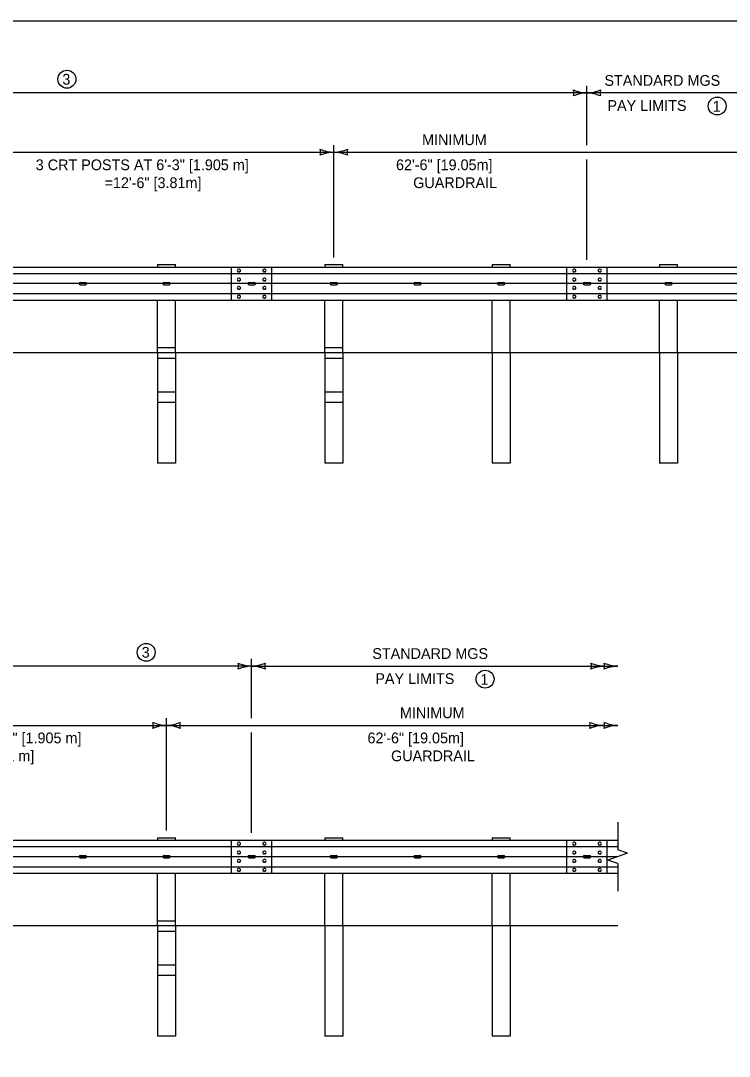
# Model space of a CAD drawing. Extents: x 49991.4 to 50021, y 49987.6 to 50011.4.
# Drawn here: x 50007.16 to 50011.12, y 49993.22 to 49999 of the extents above; entities that cross this region are included whole.
import ezdxf

# ---------------------------------------------------------------- set-up
doc = ezdxf.new("R2010")
doc.units = 0
for name, color, linetype in [('Level 1', 7, 'Continuous'), ('Level 2', 7, 'Continuous'), ('Level 3', 7, 'Continuous'), ('Level 4', 7, 'Continuous'), ('Level 5', 7, 'Continuous'), ('Level 6', 7, 'Continuous')]:
    doc.layers.add(name, color=color, linetype=linetype)

msp = doc.modelspace()

# ---------------------------------------------------------------- linework, layer by layer
at = {"layer": 'Level 1'}
for p, q in [((50007.9289, 49997.6379), (50007.9289, 49997.6246)), ((50007.9289, 49997.6379), (50008.0288, 49997.6379)), ((50008.0288, 49997.6246), (50008.0288, 49997.6379)), ((50008.8633, 49997.6379), (50008.8633, 49997.6246)), ((50008.8633, 49997.6379), (50008.9633, 49997.6379)), ((50008.9633, 49997.6246), (50008.9633, 49997.6379)), ((50009.7977, 49997.6379), (50009.7977, 49997.6246)), ((50009.7977, 49997.6379), (50009.8977, 49997.6379)), ((50009.8977, 49997.6246), (50009.8977, 49997.6379)), ((50010.7322, 49997.6379), (50010.7322, 49997.6246)), ((50010.7322, 49997.6379), (50010.8321, 49997.6379)), ((50010.8321, 49997.6246), (50010.8321, 49997.6379)), ((50000.0289, 49997.6246), (50011.2949, 49997.6246)), ((50000.0289, 49997.5886), (50011.2949, 49997.5886)), ((50008.3411, 49997.4394), (50008.3411, 49997.6239)), ((50008.3852, 49997.6123), (50008.3816, 49997.6123)), ((50008.3852, 49997.5973), (50008.3816, 49997.5973)), ((50008.5275, 49997.6123), (50008.5239, 49997.6123)), ((50008.5275, 49997.5973), (50008.5239, 49997.5973)), ((50010.2135, 49997.4394), (50010.2135, 49997.6239)), ((50010.2577, 49997.6123), (50010.2541, 49997.6123)), ((50010.2577, 49997.5973), (50010.2541, 49997.5973)), ((50010.3999, 49997.6123), (50010.3963, 49997.6123)), ((50010.3999, 49997.5973), (50010.3963, 49997.5973)), ((50007.497, 49997.5386), (50007.5262, 49997.5386)), ((50007.497, 49997.5261), (50007.5262, 49997.5261)), ((50007.9642, 49997.5386), (50007.9934, 49997.5386)), ((50007.9642, 49997.5261), (50007.9934, 49997.5261)), ((50008.3852, 49997.5624), (50008.3816, 49997.5624)), ((50008.3852, 49997.5474), (50008.3816, 49997.5474)), ((50008.3852, 49997.516), (50008.3816, 49997.516)), ((50008.4397, 49997.5386), (50008.4689, 49997.5386)), ((50008.4397, 49997.5261), (50008.4689, 49997.5261)), ((50008.5275, 49997.5624), (50008.5239, 49997.5624)), ((50008.5275, 49997.5474), (50008.5239, 49997.5474)), ((50008.5275, 49997.516), (50008.5239, 49997.516)), ((50008.8987, 49997.5386), (50008.9279, 49997.5386)), ((50008.8987, 49997.5261), (50008.9279, 49997.5261)), ((50009.3659, 49997.5386), (50009.3951, 49997.5386)), ((50009.3659, 49997.5261), (50009.3951, 49997.5261)), ((50009.8331, 49997.5386), (50009.8623, 49997.5386)), ((50009.8331, 49997.5261), (50009.8623, 49997.5261)), ((50010.2577, 49997.5624), (50010.2541, 49997.5624)), ((50010.2577, 49997.5474), (50010.2541, 49997.5474)), ((50010.2577, 49997.516), (50010.2541, 49997.516)), ((50010.3122, 49997.5386), (50010.3413, 49997.5386)), ((50010.3122, 49997.5261), (50010.3413, 49997.5261)), ((50010.3999, 49997.5624), (50010.3963, 49997.5624)), ((50010.3999, 49997.5474), (50010.3963, 49997.5474)), ((50010.3999, 49997.516), (50010.3963, 49997.516)), ((50010.7676, 49997.5386), (50010.7967, 49997.5386)), ((50010.7676, 49997.5261), (50010.7967, 49997.5261)), ((50000.0289, 49997.4761), (50011.2949, 49997.4761)), ((50008.3852, 49997.5009), (50008.3816, 49997.5009)), ((50008.3852, 49997.4661), (50008.3816, 49997.4661)), ((50008.5275, 49997.5009), (50008.5239, 49997.5009)), ((50008.5275, 49997.4661), (50008.5239, 49997.4661)), ((50010.2577, 49997.5009), (50010.2541, 49997.5009)), ((50010.2577, 49997.4661), (50010.2541, 49997.4661)), ((50010.3999, 49997.5009), (50010.3963, 49997.5009)), ((50010.3999, 49997.4661), (50010.3963, 49997.4661)), ((50000.0289, 49997.4401), (50011.2949, 49997.4401)), ((50007.9289, 49997.1457), (50007.9289, 49997.4401)), ((50008.0288, 49997.1457), (50008.0288, 49997.4401)), ((50008.3852, 49997.451), (50008.3816, 49997.451)), ((50008.5275, 49997.451), (50008.5239, 49997.451)), ((50008.8633, 49997.1457), (50008.8633, 49997.4401)), ((50008.9632, 49997.1457), (50008.9632, 49997.4401)), ((50009.7977, 49997.1457), (50009.7977, 49997.4401)), ((50009.8976, 49997.1457), (50009.8976, 49997.4401)), ((50010.2577, 49997.451), (50010.2541, 49997.451)), ((50010.3999, 49997.451), (50010.3963, 49997.451)), ((50010.7322, 49997.1457), (50010.7322, 49997.4401)), ((50010.8321, 49997.1457), (50010.8321, 49997.4401)), ((50011.2949, 49997.1457), (50000.0289, 49997.1457)), ((50000.0289, 49994.4263), (50010.4985, 49994.4263)), ((50000.0289, 49994.3903), (50010.4985, 49994.3903)), ((50007.9289, 49994.4396), (50007.9289, 49994.4263)), ((50007.9289, 49994.4396), (50008.0288, 49994.4396)), ((50008.0288, 49994.4263), (50008.0288, 49994.4396)), ((50008.3411, 49994.241), (50008.3411, 49994.4256)), ((50008.3852, 49994.414), (50008.3816, 49994.414)), ((50008.3852, 49994.3989), (50008.3816, 49994.3989)), ((50008.5275, 49994.414), (50008.5239, 49994.414)), ((50008.5275, 49994.3989), (50008.5239, 49994.3989)), ((50008.8633, 49994.4396), (50008.8633, 49994.4263)), ((50008.8633, 49994.4396), (50008.9633, 49994.4396)), ((50008.9633, 49994.4263), (50008.9633, 49994.4396)), ((50009.7977, 49994.4396), (50009.7977, 49994.4263)), ((50009.7977, 49994.4396), (50009.8977, 49994.4396)), ((50009.8977, 49994.4263), (50009.8977, 49994.4396)), ((50010.2135, 49994.241), (50010.2135, 49994.4256)), ((50010.2577, 49994.414), (50010.2541, 49994.414)), ((50010.2577, 49994.3989), (50010.2541, 49994.3989)), ((50010.3999, 49994.414), (50010.3963, 49994.414)), ((50010.3999, 49994.3989), (50010.3963, 49994.3989)), ((50007.497, 49994.3403), (50007.5262, 49994.3403)), ((50007.9642, 49994.3403), (50007.9934, 49994.3403)), ((50008.3852, 49994.3641), (50008.3816, 49994.3641)), ((50008.3852, 49994.349), (50008.3816, 49994.349)), ((50008.4397, 49994.3403), (50008.4689, 49994.3403)), ((50008.5275, 49994.3641), (50008.5239, 49994.3641)), ((50008.5275, 49994.349), (50008.5239, 49994.349)), ((50008.8987, 49994.3403), (50008.9279, 49994.3403)), ((50009.3659, 49994.3403), (50009.3951, 49994.3403)), ((50009.8331, 49994.3403), (50009.8623, 49994.3403)), ((50010.2577, 49994.3641), (50010.2541, 49994.3641)), ((50010.2577, 49994.349), (50010.2541, 49994.349)), ((50010.3122, 49994.3403), (50010.3413, 49994.3403)), ((50010.3999, 49994.3641), (50010.3963, 49994.3641)), ((50010.3999, 49994.349), (50010.3963, 49994.349)), ((50000.0289, 49994.2777), (50010.4985, 49994.2777)), ((50007.497, 49994.3278), (50007.5262, 49994.3278)), ((50007.9642, 49994.3278), (50007.9934, 49994.3278)), ((50008.3852, 49994.3176), (50008.3816, 49994.3176)), ((50008.3852, 49994.3025), (50008.3816, 49994.3025)), ((50008.4397, 49994.3278), (50008.4689, 49994.3278)), ((50008.5275, 49994.3176), (50008.5239, 49994.3176)), ((50008.5275, 49994.3025), (50008.5239, 49994.3025)), ((50008.8987, 49994.3278), (50008.9279, 49994.3278)), ((50009.3659, 49994.3278), (50009.3951, 49994.3278)), ((50009.8331, 49994.3278), (50009.8623, 49994.3278)), ((50010.2577, 49994.3176), (50010.2541, 49994.3176)), ((50010.2577, 49994.3025), (50010.2541, 49994.3025)), ((50010.3122, 49994.3278), (50010.3413, 49994.3278)), ((50010.3999, 49994.3176), (50010.3963, 49994.3176)), ((50010.3999, 49994.3025), (50010.3963, 49994.3025)), ((50000.0289, 49994.2417), (50010.4985, 49994.2417)), ((50007.9289, 49993.9473), (50007.9289, 49994.2417)), ((50008.0288, 49993.9473), (50008.0288, 49994.2417)), ((50008.3852, 49994.2677), (50008.3816, 49994.2677)), ((50008.3852, 49994.2526), (50008.3816, 49994.2526)), ((50008.5275, 49994.2677), (50008.5239, 49994.2677)), ((50008.5275, 49994.2526), (50008.5239, 49994.2526)), ((50008.8633, 49993.9473), (50008.8633, 49994.2417)), ((50008.9632, 49993.9473), (50008.9632, 49994.2417)), ((50009.7977, 49993.9473), (50009.7977, 49994.2417)), ((50009.8976, 49993.9473), (50009.8976, 49994.2417)), ((50010.2577, 49994.2677), (50010.2541, 49994.2677)), ((50010.2577, 49994.2526), (50010.2541, 49994.2526)), ((50010.3999, 49994.2677), (50010.3963, 49994.2677)), ((50010.3999, 49994.2526), (50010.3963, 49994.2526)), ((50010.4985, 49993.9473), (50000.0289, 49993.9473))]:
    msp.add_line(p, q, dxfattribs=at)
msp.add_lwpolyline([(49999.3835, 49998.9992), (50016.7501, 49998.9992), (50016.7501, 49987.7988), (49999.3835, 49987.7988)], close=True, dxfattribs=at)
for centre, start, end in [((50007.497, 49997.5324), 90, 180), ((50007.497, 49997.5324), 180, 270), ((50007.5262, 49997.5324), 360, 90), ((50007.5262, 49997.5324), 270, 0), ((50007.9642, 49997.5324), 90, 180), ((50007.9642, 49997.5324), 180, 270), ((50007.9934, 49997.5324), 360, 90), ((50007.9934, 49997.5324), 270, 0), ((50008.4397, 49997.5324), 90, 180), ((50008.4397, 49997.5324), 180, 270), ((50008.4689, 49997.5324), 360, 90), ((50008.4689, 49997.5324), 270, 0), ((50008.8987, 49997.5324), 90, 180), ((50008.8987, 49997.5324), 180, 270), ((50008.9279, 49997.5324), 360, 90), ((50008.9279, 49997.5324), 270, 0), ((50009.3659, 49997.5324), 90, 180), ((50009.3659, 49997.5324), 180, 270), ((50009.3951, 49997.5324), 360, 90), ((50009.3951, 49997.5324), 270, 0), ((50009.8331, 49997.5324), 90, 180), ((50009.8331, 49997.5324), 180, 270), ((50009.8623, 49997.5324), 360, 90), ((50009.8623, 49997.5324), 270, 0), ((50010.3122, 49997.5324), 90, 180), ((50010.3122, 49997.5324), 180, 270), ((50010.3413, 49997.5324), 360, 90), ((50010.3413, 49997.5324), 270, 0), ((50010.7676, 49997.5324), 90, 180), ((50010.7676, 49997.5324), 180, 270), ((50010.7967, 49997.5324), 360, 90), ((50010.7967, 49997.5324), 270, 0), ((50007.497, 49994.334), 90, 180), ((50007.497, 49994.334), 180, 270), ((50007.5262, 49994.334), 360, 90), ((50007.5262, 49994.334), 270, 0), ((50007.9642, 49994.334), 90, 180), ((50007.9642, 49994.334), 180, 270), ((50007.9934, 49994.334), 360, 90), ((50007.9934, 49994.334), 270, 0), ((50008.4397, 49994.334), 90, 180), ((50008.4397, 49994.334), 180, 270), ((50008.4689, 49994.334), 360, 90), ((50008.4689, 49994.334), 270, 0), ((50008.8987, 49994.334), 90, 180), ((50008.8987, 49994.334), 180, 270), ((50008.9279, 49994.334), 360, 90), ((50008.9279, 49994.334), 270, 0), ((50009.3659, 49994.334), 90, 180), ((50009.3659, 49994.334), 180, 270), ((50009.3951, 49994.334), 360, 90), ((50009.3951, 49994.334), 270, 0), ((50009.8331, 49994.334), 90, 180), ((50009.8331, 49994.334), 180, 270), ((50009.8623, 49994.334), 360, 90), ((50009.8623, 49994.334), 270, 0), ((50010.3122, 49994.334), 90, 180), ((50010.3122, 49994.334), 180, 270), ((50010.3413, 49994.334), 360, 90), ((50010.3413, 49994.334), 270, 0)]:
    msp.add_arc(centre, 0.00625, start, end, dxfattribs=at)
for centre, start_param, end_param in [((50008.3816, 49997.6048), 1.570796, 4.712389), ((50008.3852, 49997.6048), 4.712389, 7.853982), ((50008.5239, 49997.6048), 1.570796, 4.712389), ((50008.5275, 49997.6048), 4.712389, 7.853982), ((50010.2541, 49997.6048), 1.570796, 4.712389), ((50010.2577, 49997.6048), 4.712389, 7.853982), ((50010.3963, 49997.6048), 1.570796, 4.712389), ((50010.3999, 49997.6048), 4.712389, 7.853982), ((50008.3816, 49997.5549), 1.570796, 4.712389), ((50008.3816, 49997.5084), 1.570796, 4.712389), ((50008.3852, 49997.5549), 4.712389, 7.853982), ((50008.3852, 49997.5084), 4.712389, 7.853982), ((50008.5239, 49997.5549), 1.570796, 4.712389), ((50008.5239, 49997.5084), 1.570796, 4.712389), ((50008.5275, 49997.5549), 4.712389, 7.853982), ((50008.5275, 49997.5084), 4.712389, 7.853982), ((50010.2541, 49997.5549), 1.570796, 4.712389), ((50010.2541, 49997.5084), 1.570796, 4.712389), ((50010.2577, 49997.5549), 4.712389, 7.853982), ((50010.2577, 49997.5084), 4.712389, 7.853982), ((50010.3963, 49997.5549), 1.570796, 4.712389), ((50010.3963, 49997.5084), 1.570796, 4.712389), ((50010.3999, 49997.5549), 4.712389, 7.853982), ((50010.3999, 49997.5084), 4.712389, 7.853982), ((50008.3816, 49997.4585), 1.570796, 4.712389), ((50008.3852, 49997.4585), 4.712389, 7.853982), ((50008.5239, 49997.4585), 1.570796, 4.712389), ((50008.5275, 49997.4585), 4.712389, 7.853982), ((50010.2541, 49997.4585), 1.570796, 4.712389), ((50010.2577, 49997.4585), 4.712389, 7.853982), ((50010.3963, 49997.4585), 1.570796, 4.712389), ((50010.3999, 49997.4585), 4.712389, 7.853982), ((50008.3816, 49994.4065), 1.570796, 4.712389), ((50008.3852, 49994.4065), 4.712389, 7.853982), ((50008.5239, 49994.4065), 1.570796, 4.712389), ((50008.5275, 49994.4065), 4.712389, 7.853982), ((50010.2541, 49994.4065), 1.570796, 4.712389), ((50010.2577, 49994.4065), 4.712389, 7.853982), ((50010.3963, 49994.4065), 1.570796, 4.712389), ((50010.3999, 49994.4065), 4.712389, 7.853982), ((50008.3816, 49994.3566), 1.570796, 4.712389), ((50008.3852, 49994.3566), 4.712389, 7.853982), ((50008.5239, 49994.3566), 1.570796, 4.712389), ((50008.5275, 49994.3566), 4.712389, 7.853982), ((50010.2541, 49994.3566), 1.570796, 4.712389), ((50010.2577, 49994.3566), 4.712389, 7.853982), ((50010.3963, 49994.3566), 1.570796, 4.712389), ((50010.3999, 49994.3566), 4.712389, 7.853982), ((50008.3816, 49994.3101), 1.570796, 4.712389), ((50008.3852, 49994.3101), 4.712389, 7.853982), ((50008.5239, 49994.3101), 1.570796, 4.712389), ((50008.5275, 49994.3101), 4.712389, 7.853982), ((50010.2541, 49994.3101), 1.570796, 4.712389), ((50010.2577, 49994.3101), 4.712389, 7.853982), ((50010.3963, 49994.3101), 1.570796, 4.712389), ((50010.3999, 49994.3101), 4.712389, 7.853982), ((50008.3816, 49994.2602), 1.570796, 4.712389), ((50008.3852, 49994.2602), 4.712389, 7.853982), ((50008.5239, 49994.2602), 1.570796, 4.712389), ((50008.5275, 49994.2602), 4.712389, 7.853982), ((50010.2541, 49994.2602), 1.570796, 4.712389), ((50010.2577, 49994.2602), 4.712389, 7.853982), ((50010.3963, 49994.2602), 1.570796, 4.712389), ((50010.3999, 49994.2602), 4.712389, 7.853982)]:
    msp.add_ellipse(centre, major_axis=(0.00756, 0), ratio=0.998676, start_param=start_param, end_param=end_param, dxfattribs=at)
at = {"layer": 'Level 2'}
for centre in [(50007.4227, 49998.6726), (50011.054, 49998.5231), (50007.8655, 49995.4743), (50009.7577, 49995.3247)]:
    msp.add_circle(centre, 0.05, dxfattribs=at)
at = {"layer": 'Level 3'}
for p, q in [((50010.3268, 49998.3051), (50010.3268, 49998.6359)), ((50011.2949, 49998.5959), (50000.0289, 49998.5959)), ((50007.0444, 49998.2651), (50008.9133, 49998.2651)), ((50008.9133, 49997.6779), (50008.9133, 49998.3051)), ((50008.9133, 49998.2651), (50010.2868, 49998.2651)), ((50010.2868, 49998.2651), (50010.3268, 49998.2651)), ((50010.3268, 49998.2651), (50011.2949, 49998.2651)), ((50010.3268, 49997.6646), (50010.3268, 49998.2251)), ((50008.4543, 49995.1067), (50008.4543, 49995.4375)), ((50008.4543, 49995.3975), (50000.0289, 49995.3975)), ((50008.4543, 49995.3975), (50010.4985, 49995.3975)), ((50007.9788, 49994.4796), (50007.9788, 49995.1067)), ((50006.11, 49995.0667), (50007.9788, 49995.0667)), ((50007.9788, 49995.0667), (50010.4985, 49995.0667)), ((50008.4543, 49994.4662), (50008.4543, 49995.0267))]:
    msp.add_line(p, q, dxfattribs=at)
for centre, radius, start, end in [((50010.3359, 49998.818), 0.2223, 247.45601, 267.63952), ((50010.1985, 49998.5959), 0.0548, 342.13882, 17.86118), ((50010.3153, 49998.8286), 0.233, 272.82731, 292.07716), ((50010.455, 49998.5959), 0.0548, 162.13882, 197.86118), ((50010.3382, 49998.3632), 0.233, 92.82731, 112.07716), ((50010.3176, 49998.3738), 0.2223, 67.45601, 87.63952), ((50008.9224, 49998.4872), 0.2223, 247.45601, 267.63952), ((50008.7851, 49998.2651), 0.0548, 342.13882, 17.86118), ((50008.9248, 49998.0324), 0.233, 92.82731, 112.07716), ((50008.9018, 49998.4978), 0.233, 272.82731, 292.07716), ((50008.9041, 49998.043), 0.2223, 67.45601, 87.63952), ((50009.0415, 49998.2651), 0.0548, 162.13882, 197.86118), ((50008.4634, 49995.6197), 0.2223, 247.45601, 267.63952), ((50008.3261, 49995.3975), 0.0548, 342.13882, 17.86118), ((50008.4658, 49995.1648), 0.233, 92.82731, 112.07716), ((50008.4428, 49995.6303), 0.233, 272.82731, 292.07716), ((50008.4451, 49995.1754), 0.2223, 67.45601, 87.63952), ((50008.5825, 49995.3975), 0.0548, 162.13882, 197.86118), ((50010.4342, 49995.6197), 0.2223, 247.45601, 267.63952), ((50010.2969, 49995.3975), 0.0548, 342.13882, 17.86118), ((50010.4366, 49995.1648), 0.233, 92.82731, 112.07716), ((50010.5077, 49995.6197), 0.2223, 247.45601, 267.63952), ((50010.3703, 49995.3975), 0.0548, 342.13882, 17.86118), ((50010.51, 49995.1648), 0.233, 92.82731, 112.07716), ((50007.988, 49995.2889), 0.2223, 247.45601, 267.63952), ((50007.8506, 49995.0667), 0.0548, 342.13882, 17.86118), ((50007.9673, 49995.2995), 0.233, 272.82731, 292.07716), ((50008.107, 49995.0667), 0.0548, 162.13882, 197.86118), ((50010.2904, 49995.0667), 0.0548, 342.13882, 17.86118), ((50010.4301, 49995.2995), 0.233, 247.92284, 267.17269), ((50010.3703, 49995.0667), 0.0548, 342.13882, 17.86118), ((50010.51, 49995.2995), 0.233, 247.92284, 267.17269), ((50007.9903, 49994.834), 0.233, 92.82731, 112.07716), ((50007.9697, 49994.8446), 0.2223, 67.45601, 87.63952), ((50010.4278, 49994.8446), 0.2223, 92.36048, 112.54399), ((50010.5077, 49994.8446), 0.2223, 92.36048, 112.54399)]:
    msp.add_arc(centre, radius, start, end, dxfattribs=at)
at = {"layer": 'Level 4'}
for p, q in [((50008.5675, 49997.4394), (50008.5675, 49997.6239)), ((50010.44, 49997.4394), (50010.44, 49997.6239)), ((50007.9289, 49997.1748), (50008.0288, 49997.1748)), ((50008.8633, 49997.1748), (50008.9632, 49997.1748)), ((50007.9289, 49997.1457), (50007.9289, 49996.5303)), ((50007.9289, 49997.1165), (50008.0288, 49997.1165)), ((50008.0288, 49997.1457), (50008.0288, 49996.5303)), ((50008.8633, 49997.1457), (50008.8633, 49996.5303)), ((50008.8633, 49997.1165), (50008.9632, 49997.1165)), ((50008.9632, 49997.1457), (50008.9632, 49996.5303)), ((50009.7977, 49997.1457), (50009.7977, 49996.5303)), ((50009.8976, 49997.1457), (50009.8976, 49996.5303)), ((50010.7322, 49997.1457), (50010.7322, 49996.5303)), ((50010.8321, 49997.1457), (50010.8321, 49996.5303)), ((50007.9289, 49996.9287), (50008.0288, 49996.9287)), ((50008.8633, 49996.9287), (50008.9632, 49996.9287)), ((50007.9289, 49996.8704), (50008.0288, 49996.8704)), ((50008.8633, 49996.8704), (50008.9632, 49996.8704)), ((50008.0288, 49996.5303), (50007.9289, 49996.5303)), ((50008.9632, 49996.5303), (50008.8633, 49996.5303)), ((50009.8976, 49996.5303), (50009.7977, 49996.5303)), ((50010.8321, 49996.5303), (50010.7322, 49996.5303)), ((50008.5675, 49994.241), (50008.5675, 49994.4256)), ((50010.44, 49994.241), (50010.44, 49994.4256)), ((50007.9289, 49993.9765), (50008.0288, 49993.9765)), ((50007.9289, 49993.9473), (50007.9289, 49993.332)), ((50008.0288, 49993.9473), (50008.0288, 49993.332)), ((50008.8633, 49993.9473), (50008.8633, 49993.332)), ((50008.9632, 49993.9473), (50008.9632, 49993.332)), ((50009.7977, 49993.9473), (50009.7977, 49993.332)), ((50009.8976, 49993.9473), (50009.8976, 49993.332)), ((50007.9289, 49993.9182), (50008.0288, 49993.9182)), ((50007.9289, 49993.7304), (50008.0288, 49993.7304)), ((50007.9289, 49993.6721), (50008.0288, 49993.6721)), ((50008.0288, 49993.332), (50007.9289, 49993.332)), ((50008.9632, 49993.332), (50008.8633, 49993.332)), ((50009.8976, 49993.332), (50009.7977, 49993.332))]:
    msp.add_line(p, q, dxfattribs=at)
at = {"layer": 'Level 5'}
for p, q in [((50011.2949, 49997.5324), (50000.0289, 49997.5324)), ((50010.4985, 49994.334), (50000.0289, 49994.334))]:
    msp.add_line(p, q, dxfattribs=at)
at = {"layer": 'Level 6'}
for p, q in [((50010.4985, 49994.5262), (50010.4985, 49994.3729)), ((50010.5534, 49994.3535), (50010.4437, 49994.3146)), ((50010.5534, 49994.3535), (50010.4985, 49994.3729)), ((50010.4985, 49994.2951), (50010.4437, 49994.3146)), ((50010.4985, 49994.2951), (50010.4985, 49994.1416))]:
    msp.add_line(p, q, dxfattribs=at)

# ---------------------------------------------------------------- texts
at = {"layer": 'Level 2'}
for s, p in [('3', (50007.3975, 49998.6426)), ('STANDARD MGS', (50010.4242, 49998.6359)), ('PAY LIMITS', (50010.4411, 49998.4959)), ('1', (50011.0283, 49998.4916)), ('MINIMUM', (50009.406, 49998.3051)), ('3 CRT POSTS AT 6\'-3" [1.905 m]', (50007.2485, 49998.1651)), (' 62\'-6" [19.05m]', (50009.2381, 49998.1651)), (' =12\'-6" [3.81m] ', (50007.6105, 49998.0651)), ('GUARDRAIL', (50009.3563, 49998.0651)), ('3', (50007.8403, 49995.4443)), ('STANDARD MGS', (50009.128, 49995.4375)), ('PAY LIMITS', (50009.1449, 49995.2976)), ('1', (50009.732, 49995.2933)), ('MINIMUM', (50009.2823, 49995.1067)), ('3 CRT POSTS AT 6\'-3" [1.905 m]', (50006.3141, 49994.9667)), (' 62\'-6" [19.05m]', (50009.0788, 49994.9667)), (' =12\'-6" [3.81 m] ', (50006.655, 49994.8667)), ('GUARDRAIL', (50009.2327, 49994.8667))]:
    msp.add_text(s, height=0.06, dxfattribs=at).set_placement(p)

doc.saveas('drawing.dxf')
